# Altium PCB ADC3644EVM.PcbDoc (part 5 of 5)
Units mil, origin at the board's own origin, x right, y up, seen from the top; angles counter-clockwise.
Board outline 3900 x 2716.54 mil, 10 copper layers (Top Layer, L2 GND, L3 PWR, L4 GND, L5 SIG, L6 GND, L7 GND, L8 PWR, L9 GND, Bottom Layer), stack 61.2 mil thick; 368 components, 252 nets, 1539 pads, 1019 vias.
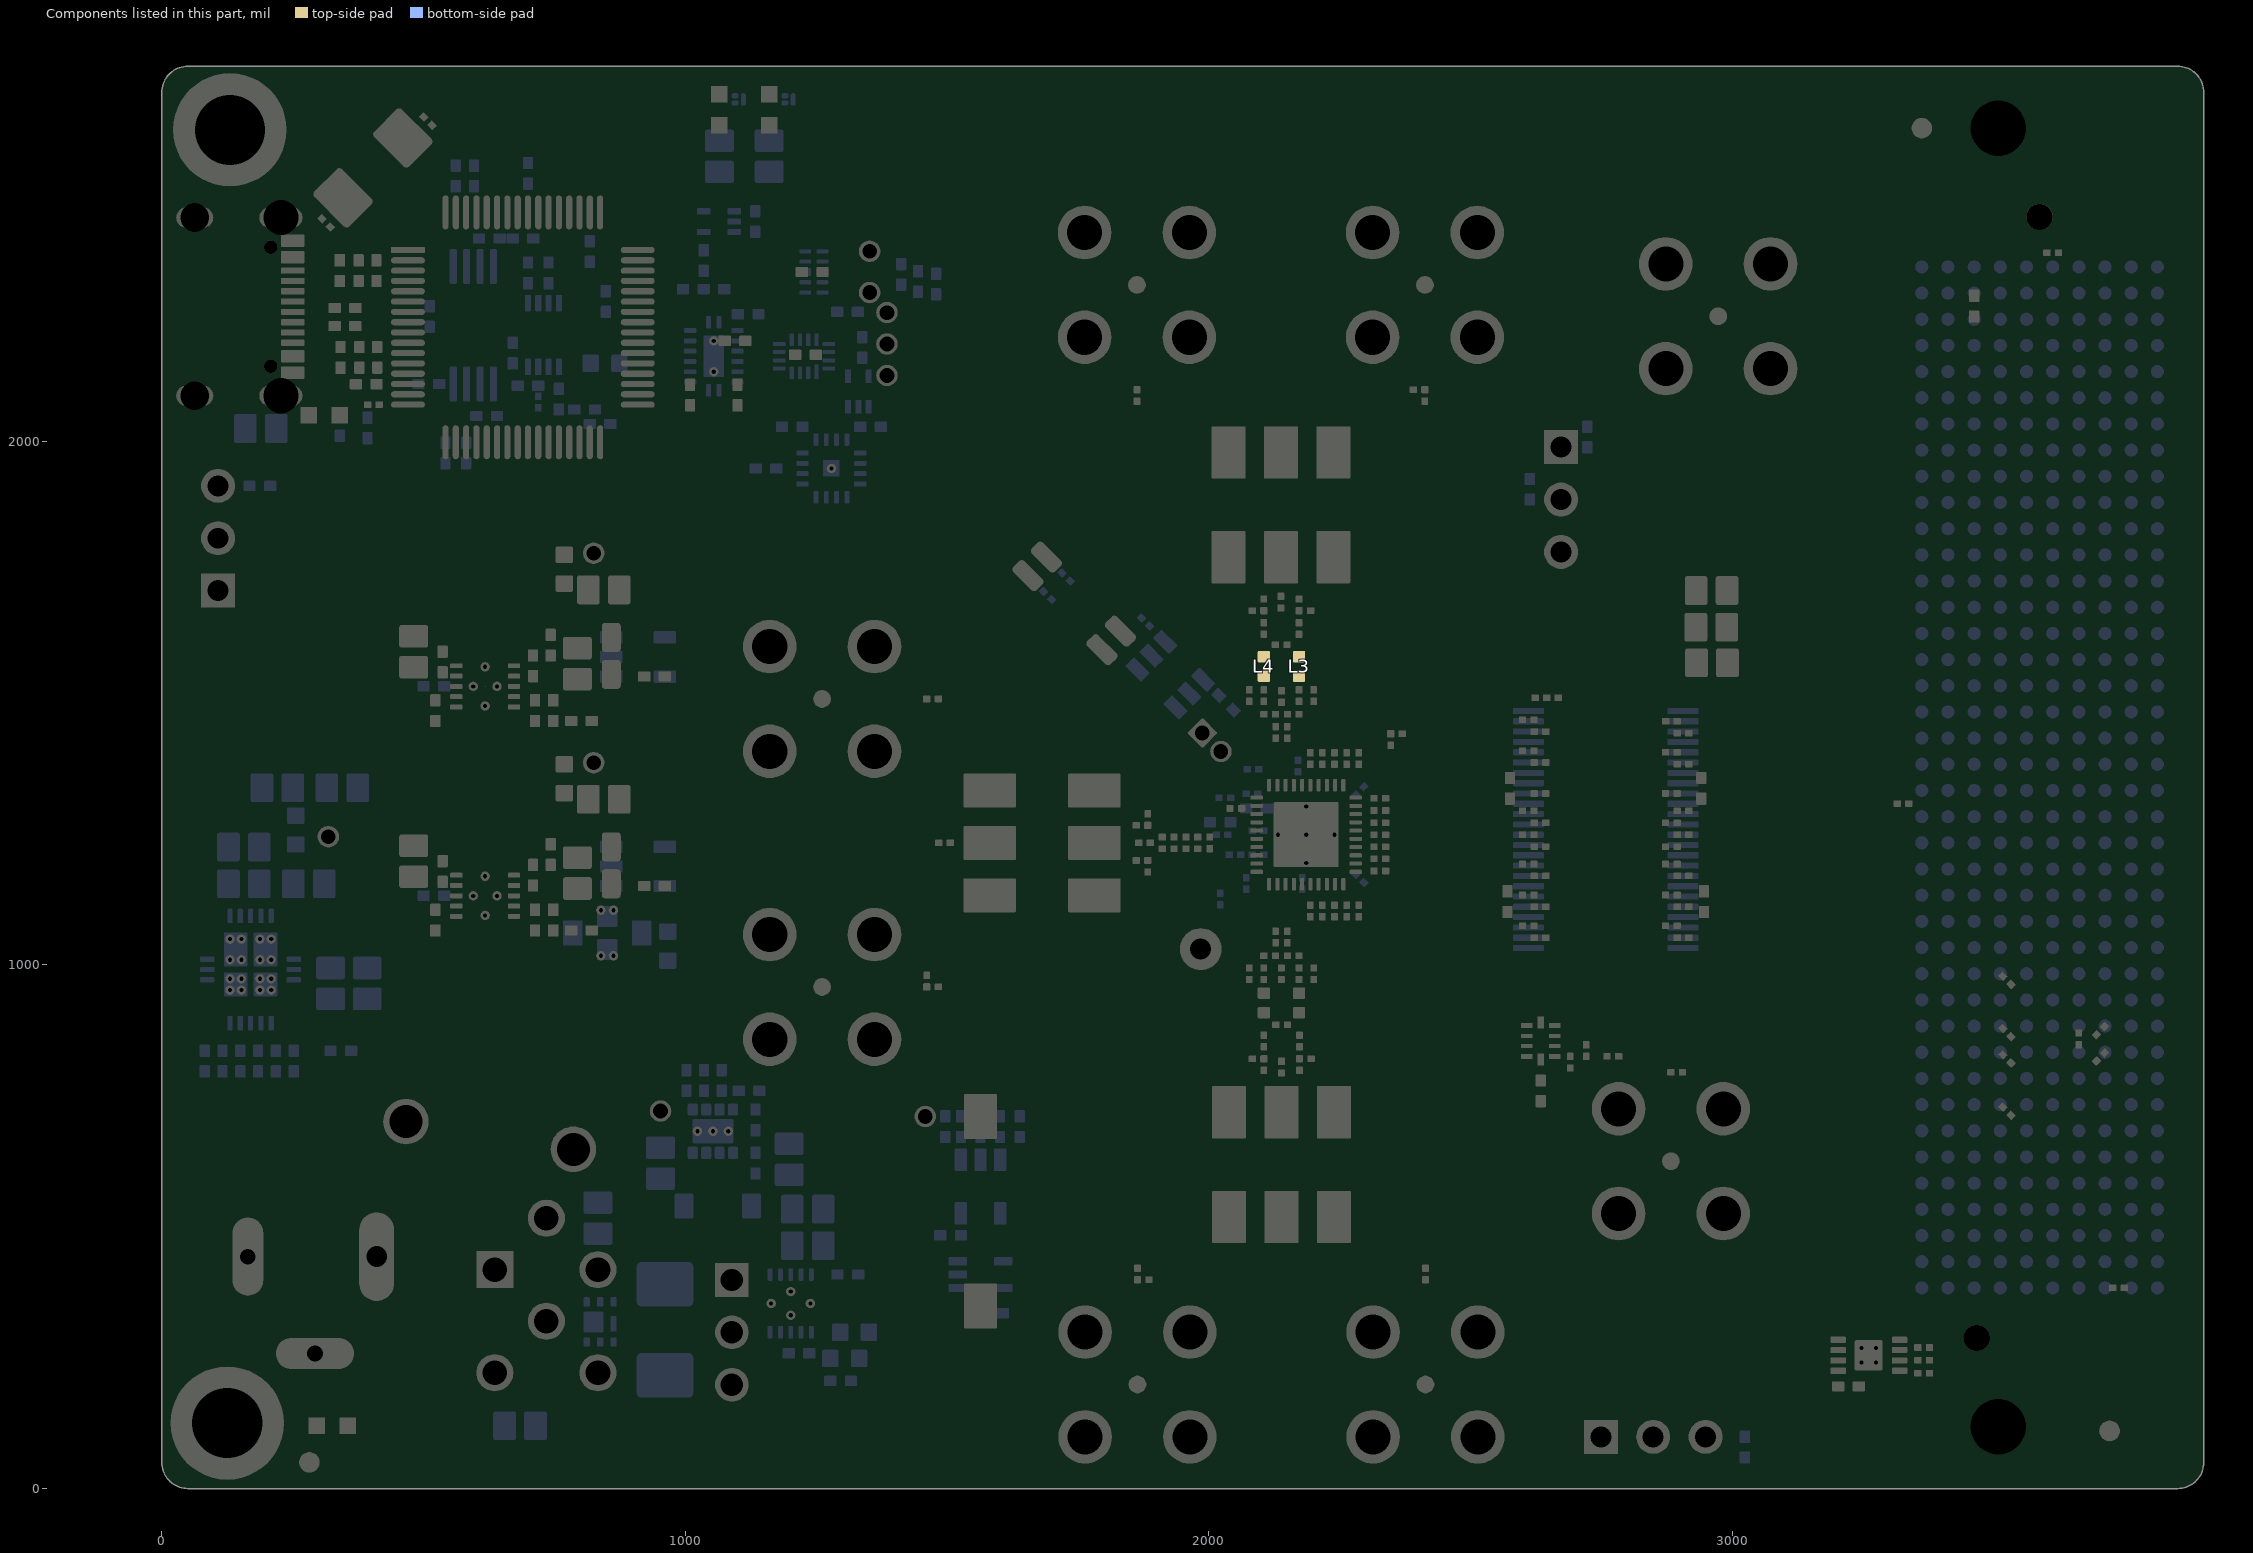
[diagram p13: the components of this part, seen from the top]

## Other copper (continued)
L3 PWR:
  pour cut-out: 2907.99,625.2 ccw(c2882.27,625.27) 2900.45,643.45 ccw(c2882.93,625.93) 2882.93,650.72 2881.55,650.72 ccw(c2881.55,625.98) 2864.06,643.47 2863.35,642.76 ccw(c2880.85,625.27) 2856.11,625.27 2856.11,624.57 ccw(c2881.56,624.57) 2863.56,606.57 2863.7,606.43 ccw(c2882.05,624.77) 2882.05,598.83 ccw(c2882.05,624.75) 2900.38,606.42 2900.75,606.79 ccw(c2883.27,624.27) 2907.99,624.27
  pour cut-out: 2998.18,2238.8 ccw(c2972.46,2238.88) 2990.65,2257.06 ccw(c2973.12,2239.54) 2973.12,2264.32 2971.75,2264.32 ccw(c2971.75,2239.59) 2954.26,2257.08 2953.55,2256.37 ccw(c2971.04,2238.88) 2946.3,2238.88 2946.3,2238.17 ccw(c2971.76,2238.17) 2953.76,2220.17 2953.9,2220.03 ccw(c2972.24,2238.38) 2972.24,2212.44 ccw(c2972.24,2238.36) 2990.58,2220.03 2990.94,2220.4 ccw(c2973.47,2237.87) 2998.18,2237.87
  pour cut-out: 2261.36,1436.62 cw(c2261.36,1447.62) 2250.36,1447.62 cw(c2261.36,1447.62) 2261.36,1458.62 cw(c2261.36,1447.62) 2272.36,1447.62 cw(c2261.36,1447.62)
  pour cut-out: 2216.16,1436.62 cw(c2216.16,1447.62) 2205.16,1447.62 cw(c2216.16,1447.62) 2216.16,1458.62 cw(c2216.16,1447.62) 2227.16,1447.62 cw(c2216.16,1447.62)
  pour cut-out: 2180.47,1425.31 cw(c2180.47,1436.31) 2169.47,1436.31 cw(c2180.47,1436.31) 2180.47,1447.31 cw(c2180.47,1436.31) 2191.47,1436.31 cw(c2180.47,1436.31)
  pour cut-out: 2198.41,1445.49 cw(c2198.41,1456.49) 2187.41,1456.49 cw(c2198.41,1456.49) 2198.41,1467.49 cw(c2198.41,1456.49) 2209.41,1456.49 cw(c2198.41,1456.49)
  pour cut-out: 2207.91,1597.91 cw(c2207.91,1608.91) 2196.91,1608.91 cw(c2207.91,1608.91) 2207.91,1619.91 cw(c2207.91,1608.91) 2218.91,1608.91 cw(c2207.91,1608.91)
  pour cut-out: 2202.84,1641 cw(c2202.84,1652) 2191.84,1652 cw(c2202.84,1652) 2202.84,1663 cw(c2202.84,1652) 2213.84,1652 cw(c2202.84,1652)
  pour cut-out: 1862.46,2330.88 cw(c1862.46,2341.88) 1851.46,2341.88 cw(c1862.46,2341.88) 1862.46,2352.88 cw(c1862.46,2341.88) 1873.46,2341.88 cw(c1862.46,2341.88)
  pour cut-out: 2412.46,2330.88 cw(c2412.46,2341.88) 2401.46,2341.88 cw(c2412.46,2341.88) 2412.46,2352.88 cw(c2412.46,2341.88) 2423.46,2341.88 cw(c2412.46,2341.88)
  pour cut-out: 2442.87,2318.28 cw(c2442.87,2329.28) 2431.87,2329.28 cw(c2442.87,2329.28) 2442.87,2340.28 cw(c2442.87,2329.28) 2453.87,2329.28 cw(c2442.87,2329.28)
  pour cut-out: 2382.06,2318.28 cw(c2382.06,2329.28) 2371.06,2329.28 cw(c2382.06,2329.28) 2382.06,2340.28 cw(c2382.06,2329.28) 2393.06,2329.28 cw(c2382.06,2329.28)
  pour cut-out: 1892.87,2318.28 cw(c1892.87,2329.28) 1881.87,2329.28 cw(c1892.87,2329.28) 1892.87,2340.28 cw(c1892.87,2329.28) 1903.87,2329.28 cw(c1892.87,2329.28)
  pour cut-out: 1832.06,2318.28 cw(c1832.06,2329.28) 1821.06,2329.28 cw(c1832.06,2329.28) 1832.06,2340.28 cw(c1832.06,2329.28) 1843.06,2329.28 cw(c1832.06,2329.28)
  pour cut-out: 921.46,1139.75 cw(c921.46,1150.75) 910.46,1150.75 cw(c921.46,1150.75) 921.46,1161.75 cw(c921.46,1150.75) 932.46,1150.75 cw(c921.46,1150.75)
  pour cut-out: 3761.42,822.27 cw(c3761.42,833.27) 3750.42,833.27 cw(c3761.42,833.27) 3761.42,844.27 cw(c3761.42,833.27) 3772.42,833.27 cw(c3761.42,833.27)
  pour cut-out: 3561.42,722.27 cw(c3561.42,733.27) 3550.42,733.27 cw(c3561.42,733.27) 3561.42,744.27 cw(c3561.42,733.27) 3572.42,733.27 cw(c3561.42,733.27)
  pour cut-out: 3560.12,570.57 cw(c3560.12,581.57) 3549.12,581.57 cw(c3560.12,581.57) 3560.12,592.57 cw(c3560.12,581.57) 3571.12,581.57 cw(c3560.12,581.57)
  pour cut-out: 3561.42,422.27 cw(c3561.42,433.27) 3550.42,433.27 cw(c3561.42,433.27) 3561.42,444.27 cw(c3561.42,433.27) 3572.42,433.27 cw(c3561.42,433.27)
  pour cut-out: 2383.73,356.91 cw(c2383.73,367.91) 2372.73,367.91 cw(c2383.73,367.91) 2383.73,378.91 cw(c2383.73,367.91) 2394.73,367.91 cw(c2383.73,367.91)
  pour cut-out: 2443.17,362.52 cw(c2443.17,373.52) 2432.17,373.52 cw(c2443.17,373.52) 2443.17,384.52 cw(c2443.17,373.52) 2454.17,373.52 cw(c2443.17,373.52)
  pour cut-out: 1978.88,358 cw(c1978.88,369) 1967.88,369 cw(c1978.88,369) 1978.88,380 cw(c1978.88,369) 1989.88,369 cw(c1978.88,369)
  pour cut-out: 1920.88,358 cw(c1920.88,369) 1909.88,369 cw(c1920.88,369) 1920.88,380 cw(c1920.88,369) 1931.88,369 cw(c1920.88,369)
  pour cut-out: 1893.17,362.52 cw(c1893.17,373.52) 1882.17,373.52 cw(c1893.17,373.52) 1893.17,384.52 cw(c1893.17,373.52) 1904.17,373.52 cw(c1893.17,373.52)
  pour cut-out: 1833.73,356.91 cw(c1833.73,367.91) 1822.73,367.91 cw(c1833.73,367.91) 1833.73,378.91 cw(c1833.73,367.91) 1844.73,367.91 cw(c1833.73,367.91)
  pour cut-out: 1824.06,1413.46 cw(c1824.06,1424.46) 1813.06,1424.46 cw(c1824.06,1424.46) 1824.06,1435.46 cw(c1824.06,1424.46) 1835.06,1424.46 cw(c1824.06,1424.46)
  pour cut-out: 2063.68,1013.29 cw(c2063.68,1024.29) 2052.68,1024.29 cw(c2063.68,1024.29) 2063.68,1035.29 cw(c2063.68,1024.29) 2074.68,1024.29 cw(c2063.68,1024.29)
  pour cut-out: 2260.18,1245.67 cw(c2260.18,1256.67) 2249.18,1256.67 cw(c2260.18,1256.67) 2260.18,1267.67 cw(c2260.18,1256.67) 2271.18,1256.67 cw(c2260.18,1256.67)
  pour cut-out: 2244.75,1214.18 cw(c2244.75,1225.18) 2233.75,1225.18 cw(c2244.75,1225.18) 2244.75,1236.18 cw(c2244.75,1225.18) 2255.75,1225.18 cw(c2244.75,1225.18)
  pour cut-out: 1980.33,1776.9 cw(c1980.33,1787.9) 1969.33,1787.9 cw(c1980.33,1787.9) 1980.33,1798.9 cw(c1980.33,1787.9) 1991.33,1787.9 cw(c1980.33,1787.9)
  pour cut-out: 1836.08,1780.35 cw(c1836.08,1791.35) 1825.08,1791.35 cw(c1836.08,1791.35) 1836.08,1802.35 cw(c1836.08,1791.35) 1847.08,1791.35 cw(c1836.08,1791.35)
  pour cut-out: 1888.18,2298.8 ccw(c1862.46,2298.88) 1880.65,2317.06 ccw(c1863.12,2299.54) 1863.12,2324.32 1861.75,2324.32 ccw(c1861.75,2299.59) 1844.26,2317.08 1843.55,2316.37 ccw(c1861.04,2298.88) 1836.3,2298.88 1836.3,2298.17 ccw(c1861.76,2298.17) 1843.76,2280.17 1843.9,2280.03 ccw(c1862.24,2298.38) 1862.24,2272.44 ccw(c1862.24,2298.36) 1880.58,2280.03 1880.94,2280.4 ccw(c1863.47,2297.87) 1888.18,2297.87
  pour cut-out: 2438.18,2298.8 ccw(c2412.46,2298.88) 2430.65,2317.06 ccw(c2413.12,2299.54) 2413.12,2324.32 2411.75,2324.32 ccw(c2411.75,2299.59) 2394.26,2317.08 2393.55,2316.37 ccw(c2411.04,2298.88) 2386.3,2298.88 2386.3,2298.17 ccw(c2411.76,2298.17) 2393.76,2280.17 2393.9,2280.03 ccw(c2412.24,2298.38) 2412.24,2272.44 ccw(c2412.24,2298.36) 2430.58,2280.03 2430.94,2280.4 ccw(c2413.47,2297.87) 2438.18,2297.87
  pour cut-out: 2387.73,198.79 ccw(c2413.44,198.72) 2395.26,180.53 ccw(c2412.79,198.06) 2412.79,173.27 2414.16,173.27 ccw(c2414.16,198) 2431.65,180.52 2432.36,181.23 ccw(c2414.86,198.72) 2439.61,198.72 2439.61,199.42 ccw(c2414.15,199.42) 2432.15,217.42 2432.01,217.56 ccw(c2413.67,199.22) 2413.67,225.16 ccw(c2413.67,199.23) 2395.33,217.57 2394.97,217.2 ccw(c2412.44,199.72) 2387.73,199.72
  pour cut-out: 1837.73,198.79 ccw(c1863.44,198.72) 1845.26,180.53 ccw(c1862.79,198.06) 1862.79,173.27 1864.16,173.27 ccw(c1864.16,198) 1881.65,180.52 1882.36,181.23 ccw(c1864.86,198.72) 1889.61,198.72 1889.61,199.42 ccw(c1864.15,199.42) 1882.15,217.42 1882.01,217.56 ccw(c1863.67,199.22) 1863.67,225.16 ccw(c1863.67,199.23) 1845.33,217.57 1844.97,217.2 ccw(c1862.44,199.72) 1837.73,199.72
  pour cut-out: 1261.18,983.77 ccw(c1261.11,958.05) 1242.92,976.24 ccw(c1260.45,958.71) 1235.66,958.71 1235.66,957.33 ccw(c1260.39,957.33) 1242.9,939.85 1243.61,939.14 ccw(c1261.11,956.63) 1261.11,931.89 1261.81,931.89 ccw(c1261.81,957.35) 1279.81,939.35 1279.95,939.49 ccw(c1261.61,957.83) 1287.55,957.83 ccw(c1261.62,957.83) 1279.95,976.16 1279.59,976.53 ccw(c1262.11,959.05) 1262.11,983.77
  pour cut-out: 1261.18,1533.77 ccw(c1261.11,1508.05) 1242.92,1526.24 ccw(c1260.45,1508.71) 1235.66,1508.71 1235.66,1507.33 ccw(c1260.39,1507.33) 1242.9,1489.85 1243.61,1489.14 ccw(c1261.11,1506.63) 1261.11,1481.89 1261.81,1481.89 ccw(c1261.81,1507.35) 1279.81,1489.35 1279.95,1489.49 ccw(c1261.61,1507.83) 1287.55,1507.83 ccw(c1261.62,1507.83) 1279.95,1526.16 1279.59,1526.53 ccw(c1262.11,1509.05) 1262.11,1533.77
  pour cut-out: 2074.96,1833.88 2074.96,1723.88 1999.96,1723.88 1999.96,1833.88
  pour cut-out: 2274.96,1833.88 2274.96,1723.88 2199.96,1723.88 2199.96,1833.88
  pour cut-out: 2274.96,2033.88 2274.96,1923.88 2199.96,1923.88 2199.96,2033.88
  pour cut-out: 2200.95,663.72 2200.95,773.72 2275.95,773.72 2275.95,663.72
  pour cut-out: 2000.95,663.72 2000.95,773.72 2075.95,773.72 2075.95,663.72
  pour cut-out: 2000.95,463.72 2000.95,573.72 2075.95,573.72 2075.95,463.72
  pour cut-out: 1726.11,1295.55 1836.11,1295.55 1836.11,1370.55 1726.11,1370.55
  pour cut-out: 1726.11,1095.55 1836.11,1095.55 1836.11,1170.55 1726.11,1170.55
  pour cut-out: 1526.11,1095.55 1636.11,1095.55 1636.11,1170.55 1526.11,1170.55
  text ".Layer_Name" at 575,-860 h60
L4 GND:
  text ".Layer_Name" at 575,-860 h60
L7 GND:
  text ".Layer_Name" at 575,-860 h60
L8 PWR:
  pour cut-out: 3220.57,234.09 cw(c3220.57,245.09) 3209.57,245.09 cw(c3220.57,245.09) 3220.57,256.09 cw(c3220.57,245.09) 3231.57,245.09 cw(c3220.57,245.09)
  pour cut-out: 3246.08,229.6 cw(c3246.08,240.6) 3235.08,240.6 cw(c3246.08,240.6) 3246.08,251.6 cw(c3246.08,240.6) 3257.08,240.6 cw(c3246.08,240.6)
  pour cut-out: 3381.1,258.36 cw(c3381.1,269.36) 3370.1,269.36 cw(c3381.1,269.36) 3381.1,280.36 cw(c3381.1,269.36) 3392.1,269.36 cw(c3381.1,269.36)
  pour cut-out: 3381.1,233.68 cw(c3381.1,244.68) 3370.1,244.68 cw(c3381.1,244.68) 3381.1,255.68 cw(c3381.1,244.68) 3392.1,244.68 cw(c3381.1,244.68)
  text ".Layer_Name" at 575,-860 h60
L9 GND:
  text ".Layer_Name" at 575,-860 h60
L5 SIG:
  pour cut-out: 2229.69,1544.16 cw(c2229.69,1555.16) 2218.69,1555.16 cw(c2229.69,1555.16) 2229.69,1566.16 cw(c2229.69,1555.16) 2240.69,1555.16 cw(c2229.69,1555.16)
  pour cut-out: 289 vertices and 0 holes, not listed, extent 1474.6,1637.11 2479.44,2122.9
  text ".Layer_Name" at 575,-860 h60
L6 GND:
  text ".Layer_Name" at 575,-860 h60
Bottom Layer:
  region net GND: 1059.37,2237.86 cw(c1060.67,2237.86) 1060.67,2239.16 1066.77,2239.16 1066.77,2239.28 1107.06,2239.28 cw(c1107.06,2235.01) 1111.34,2235.01 1111.34,2208.52 cw(c1109.9,2208.52) 1109.9,2207.08 1090.08,2207.08 1090.08,2207 1070.2,2207 cw(c1070.2,2217.83) 1059.37,2217.83
  region net 1p8V_BUFVCC: 1023.43,1037.43 ccw(c1023.43,1044.73) 1030.73,1044.73 1030.73,1079.23 ccw(c1025.3,1079.23) 1025.3,1084.67 900.29,1084.67 ccw(c900.29,1082.16) 897.78,1082.16 897.78,1039.27 ccw(c899.62,1039.27) 899.62,1037.43 929.59,1037.43 931.49,1037.43
  region net 1p8V_LVLSHIFT: 801.22,1037.43 ccw(c801.22,1039.5) 803.29,1039.5 803.29,1111.35 cw(c813.86,1111.35) 813.86,1121.91 ccw(c813.86,1129.14) 821.09,1129.14 821.09,1165.8 ccw(c817.44,1165.8) 817.44,1169.45 774.38,1169.45 ccw(c774.38,1160.96) 765.89,1160.96 765.89,1039.69 ccw(c768.16,1039.69) 768.16,1037.43
  region net NetJ3_A4,B4: 225,2165 ccw(c240,2165) 240,2150 265,2150 ccw(c265,2160) 275,2160 275,2355 ccw(c265,2355) 265,2365 240.09,2365 ccw(c240,2350) 225,2350 225,2320 cw(c205,2320) 205,2300 140,2300 ccw(c140,2280) 120,2280 120,2020 ccw(c145,2020) 145,1995 180,1995 ccw(c180,2000) 185,2000 185,2055 ccw(c180,2055) 180,2060 cw(c180,2070) 170,2070 170,2165 cw(c180,2165) 180,2175 215,2175 cw(c215,2165)
  region net GND: 1358.66,1933.73 ccw(c1358.66,1938.23) 1363.17,1938.23 1363.17,1958.63 ccw(c1358.94,1958.63) 1358.94,1962.86 1324.07,1962.86 ccw(c1324.07,1961) 1322.21,1961 1322.21,1935.65 ccw(c1324.13,1935.65) 1324.13,1933.73 1326.09,1933.73
  region net 3p3V_Utility: 1199.13,1962.86 ccw(c1199.13,1958.36) 1194.62,1958.36 1194.62,1937.96 ccw(c1198.85,1937.96) 1198.85,1933.73 1233.72,1933.73 ccw(c1233.72,1935.59) 1235.58,1935.59 1235.58,1960.93 ccw(c1233.66,1960.93) 1233.66,1962.86 1231.7,1962.86
  region net 3p3V_Utility: 1053.66,2073.3 1064.09,2073.3 ccw(c1064.09,2078.02) 1068.82,2078.02 1068.82,2104.88 1068.82,2107.09 ccw(c1066.69,2107.24) 1066.83,2109.36 1030.72,2109.36 ccw(c1030.72,2098.63) 1019.99,2098.63 1019.99,2096.93 ccw(c1028.57,2096.93) 1028.57,2088.35 cw(c1028.57,2083.37) 1033.55,2083.37 ccw(c1043.62,2083.37) 1043.62,2073.3 1044.15,2073.3 ccw(c1044.15,2097.97) 1046.76,2073.44 1046.61,2073.3
  region net DC-DC_PG: 242.05,824.31 242.05,870.61 ccw(c237.5,870.61) 237.5,875.16 231.59,875.16 cw(c231.59,877.12) 229.62,877.12 229.62,909.61 cw(c231.59,909.61) 231.59,911.57 264.07,911.57 cw(c264.07,909.8) 265.84,909.8 265.84,903.7 266.04,903.7 266.04,828.62 cw(c261.73,828.62) 261.73,824.31
  region net 2p3V: 294.81,1210.12 cw(c294.81,1214.32) 290.61,1214.32 290.61,1249.02 ccw(c270.2,1249.02) 270.2,1269.44 238.85,1269.44 cw(c238.85,1279.62) 228.67,1279.62 228.67,1420.85 cw(c235.57,1420.85) 235.57,1427.76 327.39,1427.76 cw(c327.39,1418.21) 336.94,1418.21 336.94,1281.99 ccw(c345.07,1281.99) 345.07,1273.85 cw(c345.07,1266.38) 352.54,1266.38 352.54,1217.59 cw(c345.07,1217.59) 345.07,1210.12
  region net GND: 38.05,863.68 38.05,968.87 cw(c45.17,968.87) 45.17,976 98.72,976.54 ccw(c98.72,986.95) 109.13,986.95 109.13,997.24 ccw(c99.52,996.45) 98.72,1006.06 45.17,1006.06 cw(c44.84,1012.86) 38.05,1012.53 38.26,1115.78 cw(c47.89,1115.78) 47.89,1125.41 103.58,1125.41 ccw(c103.58,1127.44) 105.61,1127.44 105.61,1182.56 148.91,1182.56 148.91,1123.39 ccw(c152.85,1123.39) 152.85,1119.46 cw(c152.85,1117.49) 154.82,1117.49 154.82,1074.55 ccw(c158.26,1074.55) 158.26,1071.11 cw(c158.26,1065.7) 163.68,1065.7 163.68,997.8 ccw(c176.56,998.24) 175.49,985.39 218.73,985.39 cw(c218.73,983.36) 220.76,983.36 220.76,884.02 cw(c211.91,884.01) 211.91,875.16 206,875.16 cw(c206,877.12) 204.03,877.13 204.03,909.64 ccw(c199.05,909.64) 199.05,914.62 114.55,914.62 ccw(c114.55,909.61) 109.54,909.61 109.54,887.21 cw(c86.02,887.2) 86.01,863.68
  region net GND: 240.5,966.69 275.71,966.69 ccw(c275.71,970.29) 279.3,970.29 cw(c281.61,970.29) 281.61,972.6 419.82,972.6 419.82,1015.85 283.36,1015.85 cw(c263.68,1015.9) 263.68,996.22 240.42,996.22 ccw(c240.42,994.29) 238.48,994.29 238.48,971.09 238.48,968.57 ccw(c240.35,968.57) 240.35,966.7
  region net 12V: 238.48,955.68 cw(c239.65,955.68) 239.65,956.85 419.82,956.85 419.82,913.54 294.7,913.54 ccw(c280.92,913.54) 280.92,927.32 240.43,927.32 cw(c240.25,929.09) 238.48,928.91
  region net NetC11_2: 164.66,1213.92 164.66,1252.86 cw(c170.05,1252.86) 170.05,1258.25 267.23,1258.25 cw(c267.23,1252.56) 272.93,1252.56 272.93,1014.92 cw(c264.07,1014.92) 264.07,1006.06 240.45,1006.06 227.58,1006.06 ccw(c227.58,999.24) 220.76,999.24 cw(c218.73,999.24) 218.73,997.2 177.53,997.2 cw(c177.53,999.24) 175.49,999.24 175.49,1070.83 ccw(c166.43,1070.83) 166.63,1079.88 cw(c166.63,1081.88) 166.55,1079.88 ccw(c166.55,1079.78) 166.53,1079.88 cw(c166.63,1081.85) 164.66,1081.85 164.66,1213.87 cw(c174.84,1213.87)
  pour cut-out: 109.54,877.13 109.54,909.61 cw(c114.55,909.61) 114.55,914.62 199.05,914.62 cw(c199.05,909.64) 204.03,909.64 204.03,877.13
  region net 12V: 1085.37,563.37 cw(c1085.37,544.99) 1103.76,544.99 1103.76,522.42 ccw(c1110.83,522.42) 1110.83,515.35 1137.61,515.35 cw(c1137.61,495.83) 1157.12,495.83 1157.12,400 ccw(c1160.29,400) 1160.29,396.83 1203.8,396.83 ccw(c1203.8,398.96) 1205.94,398.97 1205.94,426.28 cw(c1215.74,426.28) 1215.74,436.08 1225.69,436.08 1225.69,616.62 ccw(c1221.29,616.62) 1221.29,621.02 1175.14,621.02 ccw(c1175.14,607.73) 1175.08,621.02 1087.64,621.02 cw(c1087.64,633.52) 1075.13,633.52 1075.13,648.1 ccw(c1070.28,648.1) 1070.28,652.96 1060.06,652.96 ccw(c1060.06,648.35) 1055.45,648.35 1055.45,567 ccw(c1059.07,567) 1059.07,563.37
  region net NetF1_1: 679.61,584.11 680.09,584.03 825.56,584.03 ccw(c825.56,617.33) 858.86,617.33 858.86,707.08 ccw(c852.59,707.08) 852.59,713.36 577.66,713.36 ccw(c577.66,693) 557.31,693 557.31,585.32 cw(c517.94,585.32) 517.94,545.95 389.99,545.95 ccw(c389.99,516.43) 360.46,516.43 360.46,378.63 ccw(c409.67,378.63) 409.67,329.42 618.33,329.42 ccw(c618.33,382.57) 671.48,382.57 671.48,571.54 cw(c685.26,571.54)
  region net EXTGND: 101.33,287.03 ccw(c124.78,287.03) 124.78,263.57 182.11,263.57 cw(c182.11,238.64) 207.04,238.64 ccw(c229.51,238.64) 229.51,216.17 531.41,216.17 cw(c531.41,188.72) 558.86,188.72 ccw(c573.91,188.72) 573.91,173.67 669.83,173.67 ccw(c669.83,189.11) 685.26,189.11 685.26,287.03 633.15,287.03 cw(c633.15,296.61) 633.1,287.03 685.26,287.03 ccw(c659.66,284.13) 656.76,309.73 350.62,309.73 cw(c350.62,319.58) 340.77,319.58 340.77,496.72 340.87,496.74 340.87,530.41 340.87,547.77 cw(c410.43,547.78) 410.43,617.33 491.45,617.33 ccw(c491.45,662.2) 536.33,662.2 536.33,740.36 ccw(c493.33,740.36) 493.33,783.36 391.33,783.36 ccw(c391.32,678.36) 286.38,681.78 286.33,681.8 cw(c143.89,681.79) 144.13,539.36 113.59,539.36 ccw(c113.59,527.1) 101.33,527.1
  region net NetR1_2: 1208.88,248.56 1208.88,268.25 cw(c1208.88,271.24) 1205.89,271.24 1205.89,307.98 1205.94,307.98 1205.94,308.31 ccw(c1204.03,308.31) 1204.03,310.21 1159.38,310.21 1129.39,310.21 cw(c1129.39,318.62) 1120.99,318.62 ccw(c1109.11,318.62) 1109.11,330.49 1062.92,330.49 ccw(c1062.92,324.33) 1056.76,324.33 1056.76,256.47 ccw(c1064.67,256.47) 1064.67,248.56 1185.4,248.56
  region net GND: 858.86,270.91 878.85,270.91 ccw(c878.85,278.48) 886.42,278.48 886.42,315.7 ccw(c872.93,315.7) 872.93,329.18 857.49,329.18 857.49,328.61 856.92,328.61 856.92,272.86 ccw(c858.86,272.86)
  region net NetC1_2: 695.1,299.89 ccw(c724.63,299.89) 724.63,270.36 cw(c724.63,231) 764,230.99 764,211.31 ccw(c793.5,211.31) 764.08,209.13 ccw(c767.36,208.4) 764,208.4 ccw(c798.74,208.4) 798.74,173.67 1005.49,173.67 996.33,188.72 996.32,255.77 850.23,255.77 cw(c850.93,263.53) 843.14,263.53 843.14,362.9 ccw(c840.64,362.91) 840.64,365.4 787.07,365.4 cw(c787.07,378.63) 773.85,378.63 773.85,506.59 cw(c793.53,506.59) 774.03,509.31 774.03,508.51 cw(c789.84,508.51) 774.07,509.54 cw(c793.53,506.59) 779.95,520.84 cw(c789.84,508.51) 789.84,524.31 805.34,524.31 805.34,524.3 860.46,524.3 ccw(c860.46,526.27) 862.43,526.27 862.43,536.11 862.43,561.2 862.43,564.87 ccw(c859.69,564.87) 859.69,567.61 701.51,567.61 ccw(c701.51,561.2) 695.1,561.2
  region net NetC5_2: 1311.06,281.67 1311.06,315.14 1268.26,315.14 ccw(c1268.26,313.4) 1266.53,313.4 cw(c1263.34,313.4) 1263.34,310.21 1237.85,310.21 ccw(c1237.85,308.23) 1235.86,308.23 1235.86,288.58 ccw(c1237.85,288.58) 1237.85,286.59 1264.6,286.59 cw(c1264.6,284.62) 1266.57,284.62 ccw(c1269.52,284.62) 1269.52,281.67 1279.56,281.67
  region net NetC4_2: 1216.2,281.52 ccw(c1217.68,281.52) 1217.68,280.04 cw(c1217.68,278.79) 1218.93,278.79 1218.93,251.79 ccw(c1222.16,251.79) 1221.52,248.62 1221.52,248.56 1235.02,248.56 cw(c1235.02,232.36) 1251.22,232.36 1251.22,210.14 ccw(c1265.58,210.14) 1265.58,195.78 1288.75,195.78 1288.75,228.14 cw(c1292.28,228.14) 1292.28,231.67 1292.28,265.14 1251.3,265.14 cw(c1251.3,268.18) 1248.25,268.18 1245.58,268.18 cw(c1245.58,288.17) 1225.58,288.17 1225.58,308.49 ccw(c1223.88,308.49) 1223.88,310.21 1217.89,310.21 ccw(c1217.89,308.52) 1216.2,308.52 1216.2,289.12 1216.18,289.12 1216.18,288.01 ccw(c1217.47,288.01) 1216.2,287.78
  region net 3p3V_Utility: 1009.61,629.34 1020.57,629.34 ccw(c1020.57,632.67) 1023.91,632.67 1023.91,650.05 ccw(c1020.91,650.05) 1020.91,652.96 1008.74,652.96 cw(c1008.74,660.8) 1000.91,660.8 1000.91,705.19 cw(c1007.76,705.19) 1007.76,712.04 1020.08,712.04 ccw(c1020.08,715.91) 1023.95,715.91 1023.95,731.69 ccw(c1020,731.69) 1020,735.64 1007.66,735.64 1007.66,735.6 981.49,735.6 cw(c981.49,744.6) 972.5,744.6 ccw(c968.34,744.6) 968.34,748.75 932.5,748.75 ccw(c932.5,741.19) 924.94,741.19 924.94,632.96 ccw(c928.49,632.96) 928.49,629.41 1017.11,629.41
  region net NetC1_1: 793.53,382.57 ccw(c797.47,382.57) 797.47,378.63 847.74,378.63 cw(c847.74,369.45) 856.92,369.45 856.92,351.27 ccw(c860.5,351.27) 860.5,347.69 1015.01,347.69 1030.73,347.69 ccw(c1030.73,356.54) 1039.59,356.54 cw(c1049.53,356.54) 1049.53,366.48 1120.99,366.48 1120.99,466.92 ccw(c1101.01,466.92) 1101.01,486.9 921.48,486.9 cw(c921.48,496.74) 911.64,496.74 ccw(c899.83,496.74) 899.83,508.55 805.34,508.55 ccw(c805.34,496.74) 793.53,496.74
  region net 3p3V_Utility: 532.01,1988.54 ccw(c534.67,1988.54) 534.67,1985.88 603.73,1985.88 ccw(c603.73,1994.84) 612.68,1994.84 612.68,2056.34 ccw(c610.86,2056.34) 610.86,2058.16 540.49,2058.16 ccw(c540.55,2049.62) 532.01,2049.77 532.01,1999.41
  region net 3p3V_Utility: 519.77,2097.73 531.52,2097.73 cw(c531.52,2079.52) 549.72,2079.52 ccw(c553.17,2079.52) 553.17,2076.08 560.06,2076.08 ccw(c560.06,2079.52) 563.5,2079.52 563.5,2139.56 ccw(c560.06,2139.56) 560.06,2143.01 553.17,2143.01 ccw(c553.17,2139.56) 549.72,2139.56 cw(c531.52,2139.56) 531.52,2121.35 519.77,2121.35
  region net GND: 638.66,2076.08 ccw(c638.66,2089.5) 652.09,2089.5 652.09,2129.23 ccw(c638.31,2129.23) 638.31,2143.01 629.94,2143.01 ccw(c629.94,2139.56) 626.5,2139.56 626.5,2079.52 ccw(c629.94,2079.52) 629.94,2076.08
  pour cut-out: 264 vertices and 0 holes, not listed, extent 2633.31,840.66 3489.35,2225.71
  pour cut-out: 494 vertices and 0 holes, not listed, extent 2648.54,805.06 3554.21,1460.91
  pour cut-out: 278 vertices and 0 holes, not listed, extent 2772.2,1087.03 3689.35,2126.06
  pour cut-out: 2582.24,1434.61 2576.45,1428.81 2576.45,1413.92 2568.49,1413.92 2559.43,1422.98 2559.43,1445.65
  pour cut-out: 2555,1330 2555,1291.25 2557.83,1288.42 2575.08,1288.42 2575.08,1322.02 2580.6,1327.54
  pour cut-out: 2560,1110 2556.51,1106.51 2556.51,1071.63 2584.91,1071.63 2586.77,1073.49 2586.77,1111
  pour cut-out: 2341.76,1166.31 2341.76,1135.32 2337.13,1130.69 2368.96,1130.69 2368.96,1168.77 2370.24,1170.06
  pour cut-out: 2565,1230 2565.89,1229.11 2580.6,1229.11 2580.6,1190.74 2579.6,1189.74 2563.29,1189.74
  pour cut-out: 2871.14,1222.34 2871.14,1194.4 2877.52,1200.78 2885.31,1200.78 2885.31,1218.07
  pour cut-out: 2860,1445 2860,1302.92 2870.62,1292.3 2883.58,1305.27 2883.58,1451.55
  pour cut-out: 3340,2040 3348.51,2048.51 3348.51,2120.92 3323.74,2120.92 3311.09,2108.27 3333.44,2085.91 3333.44,2040.13
  pour cut-out: 3186.24,830.5 3186.24,824.45 3223.95,786.75 3209.85,772.65 3186.24,772.65 3186.24,802.16 3165.55,822.85
  pour cut-out: 3350,1110 3350,1065.21 3337.37,1077.84 3337.37,1108.27
  pour cut-out: 3344.84,1226.4 3339.78,1221.34 3339.78,1158.27 3323.27,1158.27 3325.45,1160.45 3325.45,1219.45
  pour cut-out: 3350,1660 3346.86,1656.87 3346.86,1608.27 3335.97,1608.27
  pour cut-out: 2955,1230 2955,1191 2956.26,1189.74 2975.15,1189.74 2975.15,1226.13 2972.17,1229.11
  pour cut-out: 2950,1290 2950,1323.95 2953.58,1327.54 2962.52,1318.6 2962.52,1288.17
  pour cut-out: 2950,1405 2950.77,1405.77 2950.77,1470.35 2957.73,1470.35 2966.06,1462.02 2966.06,1406.28
  pour cut-out: 3348.93,1881.6 3348.93,1945.66 3336.33,1958.27 3330.56,1952.49 3330.56,1898.92 3349.17,1880.31
  pour cut-out: 3345,1745 3348.73,1748.73 3348.73,1808.27 3340.02,1808.27 3334.72,1802.97 3334.72,1749.03
  pour cut-out: 190 vertices and 0 holes, not listed, extent 2134.5,1391.36 2479.44,1685.35
  region net GND: 2086.16,1331.53 2086.16,1320.62 2098.76,1320.62 2098.76,1278.94 2122.38,1278.94 2122.38,1333.22 2086.3,1333.22 2086.3,1332.54
  pour cut-out: 81.91,1006.06 81.91,1006.07 86.89,1006.06 86.9,1006.06 100.61,1006.03 104.19,1004.88 107.07,1002.45 108.79,999.1 109.13,997.24 109.13,986.95 108.93,984.92 107.38,981.17 104.5,978.29 100.75,976.74 98.72,976.54 81.91,976.53 81.91,976.55 73.2,976.57 69.62,977.71 66.74,980.15 65.02,983.5 64.68,985.36 64.68,995.64 64.88,997.68 66.43,1001.43 69.31,1004.3 73.06,1005.86 75.09,1006.06
  text ".Layer_Name" at 577,-858.49 h60
Multi-Layer:
  pour cut-out: 1334.01,1842.77 cw(c1334.01,1853.77) 1323.01,1853.77 cw(c1334.01,1853.77) 1334.01,1864.77 cw(c1334.01,1853.77) 1345.01,1853.77 cw(c1334.01,1853.77)
  pour cut-out: 1244.37,1882.18 cw(c1244.37,1893.18) 1233.37,1893.18 cw(c1244.37,1893.18) 1244.37,1904.18 cw(c1244.37,1893.18) 1255.37,1893.18 cw(c1244.37,1893.18)

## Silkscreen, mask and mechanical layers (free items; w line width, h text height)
Top Overlay:
  drawing of 231 lines, arcs and shapes, not listed
  text "POWER / GOOD" at 1239.25,2560 h90
  text "ADC3660/4xEVM / RevG" at 2530,2485.61 h60
  text "DUT / SPI" at 1641.44,2105 h70 r90
  text "CTRL" at 997.24,1992.43 h60
  text "HIGH" at 997.23,1950.17 h60
  text "LOW" at 1129.73,1950.17 h60
  text "REF" at 1258.89,1950.47 h60
  text "CLK" at 1378.89,1950.47 h60
  text "ON" at 1032.39,1911.47 h30
  text "OFF" at 1157.39,1911.47 h30
  text "EXT" at 1287.39,1911.47 h30
  text "DIFF" at 1397.39,1911.47 h30
  text "ON" at 1032.39,1851.47 h30
  text "ON" at 1157.39,1851.47 h30
  text "INT" at 1287.39,1851.47 h30
  text "DIFF" at 1397.39,1851.47 h30
  text "OFF" at 1032.39,1795.67 h30
  text "ON" at 1157.39,1795.67 h30
  text "INT" at 1287.39,1795.67 h30
  text "SE" at 1397.39,1795.67 h30
  text "DUT OPTION" at 2900,1750 h100
  text "ADC3660" at 3035,1690 h50
  text "ADC3644" at 3035,1620 h50
  text "ADC3643" at 3035,1550 h50
  text ".Layer_Name" at 577,-858.49 h60
Bottom Overlay:
  lines w7: 1290,2305 1305,2290 ; 1290,2380 1290,2370 1305,2355 1305,2290 ; 1320,2305 1305,2290 ; 1419,2259.6 1464,2259.6
  text ".Layer_Name" at 577,-858.49 h60
Top Paste:
  text ".Layer_Name" at 577,-858.49 h60
Bottom Paste:
  text ".Layer_Name" at 577,-858.49 h60
Top Solder:
  text ".Layer_Name" at 577,-858.49 h60
  text ".Layer_Name" at 577,-858.49 h60
Bottom Solder:
  text ".Layer_Name" at 577,-858.49 h60
Drill Guide:
  text ".Layer_Name" at 577,-858.49 h60
M1 Board Outline:
  lines w5: 0,50 ccw(c50,50) 50,0 100,0 3850,0 ccw(c3850,50) 3900,50 3900,100 3900,2616.53 3900,2666.54 ccw(c3850,2666.54) 3850,2716.54 100,2716.54 50,2716.54 ccw(c50,2666.54) 0,2666.54 0,2616.53 0,100 0,50
  text ".Layer_Name" at 577,-858.49 h60
M2 Board Dimensions:
  rectangle: 125,-400 500,-275
  rectangle: 0,-275 125,-150
  lines w7: 0,-275 1000,-275 ; 125,-400 125,-150 ; 250,-400 250,-150 ; 500,-400 500,-150 ; 750,-400 750,-150 ; 0,-400 0,-150 1000,-150 1000,-400 0,-400
  text ".Layer_Name" at 577,-858.49 h60
M3 3D STEP Top:
  text ".Layer_Name" at 577,-858.49 h60
M4 3D STEP Bottom:
  text ".Layer_Name" at 577,-858.49 h60
M5 Assembly Top:
  lines w10: -292,-930.17 6308,-930.17 ; -292,-726.83 6310,-726.83 ; -292,-523.5 -292,-1133.5 3713,-1133.5 6310,-1133.5 6310,-523.5 -291.5,-523.5 -291.5,-1133.5 1284,-1133.5 ; 2173,-1133.5 2173,-523.5 ; 3440,-726.83 3440,-523.5 ; 4280,-726.83 4280,-523.5 ; 4902,-1140 4902,-937.17
  text "COMPONENTS MARKED 'DNP' SHOULD NOT BE POPULATED." at 1153.5,-318.5 h60
  text "ASSEMBLY VARIANT:" at 1153,-434 h60
  text ".VariantName" at 2189,-434 h60
  text "PCB VIEWED FROM TOP SIDE" at -228.5,-655.67 h60
  text "BOARD #:" at 2248,-655.67 h60
  text ".PRJ_Number" at 2793.5,-655.67 h60
  text "REV:" at 3638,-655.67 h60
  text ".PCB_Rev" at 3929.5,-655.67 h60
  text "SVN REV:" at 4476,-655.67 h60
  text ".VersionControl_RevNumber" at 4982,-655.67 h60
  text "PLOT NAME =" at -228.5,-1064.34 h60
  text ".plot_File_Name" at 577,-1064.34 h60
  text "GENERATED    :" at 2250,-1064.34 h60
  text ".Print_Date" at 3119.5,-1064.34 h60
  text ".Print_Time" at 3848.5,-1064.34 h60
  text "TEXAS INSTRUMENTS" at 5113,-1064.34 h60
M6 Assembly Bottom:
  lines w10: -292.5,-727.33 6309.5,-727.33 ; -290.5,-930.67 6309.5,-930.67 ; 1115.5,-1140.5 1115.5,-937.67 ; 1737.5,-727.33 1737.5,-524 ; 2577.5,-727.33 2577.5,-524 ; 3844.5,-1134 3844.5,-524 ; 4733.5,-1134 6309,-1134 6309,-524 -292.5,-524 -292.5,-1134 2304.5,-1134 6309.5,-1134 6309.5,-524
  text "COMPONENTS MARKED 'DNP' SHOULD NOT BE POPULATED." at 6102,-318 h60
  text ".VariantName" at 5058,-434 h60
  text "ASSEMBLY VARIANT:" at 6097,-434 h60
  text ".VersionControl_RevNumber" at 1035.5,-656.17 h60
  text "SVN REV:" at 1541.5,-656.17 h60
  text ".PCB_Rev" at 2088,-656.17 h60
  text "REV:" at 2379.5,-656.17 h60
  text ".PRJ_Number" at 3224,-656.17 h60
  text "BOARD #:" at 3769.5,-656.17 h60
  text "PCB VIEWED FROM BOTTOM SIDE" at 6246,-656.17 h60
  text "TEXAS INSTRUMENTS" at 904.5,-1064.84 h60
  text ".Print_Time" at 2169,-1064.84 h60
  text ".Print_Date" at 2898,-1064.84 h60
  text "GENERATED    :" at 3767.5,-1064.84 h60
  text ".plot_File_Name" at 5440.5,-1064.84 h60
  text "PLOT NAME =" at 6246,-1064.84 h60
M9 Title Sheet:
  drawing of 56 lines, arcs and shapes, not listed
  text "1" at 1058.34,13381.39 h70
  text "2" at 4384,13381.39 h70
  text "3" at 7714,13381.39 h70
  text "4" at 11049,13381.39 h70
  text "5" at 14374,13381.39 h70
  text "6" at 17709,13381.39 h70
  text "A" at -463,11603.39 h70
  text "A" at 19237,11603.39 h70
  text "B" at -463,7853.39 h70
  text "B" at 19237,7853.39 h70
  text "C" at -463,4103.39 h70
  text "C" at 19237,4103.39 h70
  text "D" at -463,353.39 h70
  text "D" at 19237,353.39 h70
  text "PROJECT TITLE:" at 16143,268.39 h45
  text ".PRJ_Title" at 16193,135.06 h70
  text "DESIGNED FOR:" at 16143,-32.61 h45
  text ".PRJ_Customer" at 16193,-172.61 h70
  text "FILE NAME:" at 16143,-332.61 h45
  text ".PCB_File_Name_No_Path" at 16193,-452.61 h70
  text "Texas Instruments (TI) and/or its licensors do not warrant the accuracy or completeness of this specification" at 11173.5,-614.45 h45
  text "ENGINEER:" at 16143,-622.61 h45
  text "LAYOUT BY:" at 17648,-622.61 h45
  text "or any information contained therein. TI and/or its licensors do not warrant that this design will meet" at 11128.51,-727.11 h45
  text ".PRJ_Engineer" at 16193,-777.6 h70
  text ".PCB_Layout" at 17698.5,-777.6 h70
  text "the specifications, will be suitable for your application or fit for any particular purpose, or will operate in" at 11128.51,-839.78 h45
  text ".Layer_Name" at 577,-858.49 h60
  text "ALTIUM DESIGNER VERSION:" at 17648,-932.61 h45
  text "an implementation. TI and/or its licensors do not warrant that the design is production worthy. You should" at 11128.51,-952.44 h45
  text "completely validate and test your design implementation to confirm the system functionality for your application." at 11173.5,-1065.11 h45
  text ".print_Scale" at 16193,-1065.94 h70
  text ".Application_BuildNumber" at 17698.5,-1065.94 h70
  text "1" at 1058.34,-1318.61 h70
  text "2" at 4384,-1318.61 h70
  text "3" at 7714,-1318.61 h70
  text "4" at 11049,-1318.61 h70
  text "5" at 14374,-1318.61 h70
  text "6" at 17709,-1318.61 h70
M10 Fab Notes:
  drawing of 213 lines, arcs and shapes, not listed
  text "M10 Fab Notes" at 16103.19,9538.99 h60
  text "DESIGN INFORMATION" at 17181.52,9421.87 h60
  text "MIN. TRACK WIDTH:" at 16536.96,9289.74 h60
  text "4" at 17633.2,9289.74 h60
  text "MIL" at 17787.96,9289.74 h60
  text "MIN. CLEARANCE:" at 16536.96,9165.62 h60
  text "MIL" at 17787.96,9165.62 h60
  text "5" at 17633.42,9163.98 h60
  text "MIN. VIA PAD SIZE:" at 16536.96,9041.49 h60
  text "18" at 17603.21,9041.49 h60
  text "MIL" at 17787.96,9041.49 h60
  text "0.05mm (2MIL)" at 17231.96,8911.59 h60
  text "MINIMUM ANNULAR RING" at 16207.73,8903.37 h60
  text "EXTERNAL" at 17939.96,8903.37 h60
  text "PER" at 16407.73,8793.24 h60
  text "IPC-D-275 CLASS 2 LEVEL C" at 16627.73,8793.24 h60
  text "MIL, HOLES" at 18115.96,8692.76 h60
  text "+/-" at 17723.5,8684.18 h60
  text "+/-" at 18577.5,8684.18 h60
  text "REGISTRATION TOLERANCES:" at 16207.73,8683.11 h60
  text "METAL" at 17407.5,8683.11 h60
  text "5" at 17983.7,8683.12 h60
  text "3" at 18816.7,8683.12 h60
  text "MIL" at 18932.96,8683.11 h60
  text "HOLE SIZE TOLERANCE (UNLESS OTHERWISE SPECIFIED):" at 16207.73,8584.8 h60
  text "+/-" at 18577.5,8581.92 h60
  text "3" at 18816.7,8580.86 h60
  text "MIL" at 18932.96,8580.86 h60
  text "MATERIAL:" at 16132.96,8443.21 h60
  text "UNIFORM STACKUP" at 17867.01,8348.29 h60
  text "X" at 17725,8345 h60
  text "HYBRID STACKUP" at 16841.48,8341.02 h60
  text "ISOLA FR408HR" at 16547.68,8177.37 h60
  text "X" at 16403.5,8170.36 h60
  text "Megtron 4    Isola I-Speed" at 16538.93,7976.12 h60
  text "OR" at 16988.92,7976.12 h60
  text "Megtron6    Isola MT-40    Nelco MW-1000" at 16538.93,7779.27 h60
  text "OR" at 16940.28,7779.27 h60
  text "OR" at 17639.01,7779.27 h60
  text "OTHER" at 16578.93,7582.42 h60
  text "X" at 16756.39,7385.94 h60
  text "62 MIL (1.6mm) +/-10%" at 16877.21,7384.84 h60
  text "92 MIL  +/-10%" at 18453.18,7384.84 h60
  text "THICKNESS:" at 16210.88,7376.62 h60
  text "OTHER" at 18162.11,7376.62 h60
  text "TOLERANCE:" at 16210.88,7238.3 h60
  text "X" at 17059.11,7238.3 h60
  text "ANSI IPC-6012 TYPE 3 CLASS 2" at 17237.12,7238.3 h60
  text "OTHER +/-" at 17237.11,7094.11 h60
  text "BOW & TWIST:" at 16210.88,6948.92 h60
  text "X" at 17059.11,6948.92 h60
  text "ANSI IPC-6012 TYPE 3 CLASS 2" at 17237.12,6948.92 h60
  text "OTHER +/-" at 17237.11,6802.23 h60
  text "DRILLING:" at 16136.11,6671.61 h60
  text "NC_DRILL FILES" at 17897.11,6566.42 h60
  text "REFERENCE:" at 16210.88,6562.48 h60
  text "X" at 16868.11,6562.39 h60
  text "AS SHOWN" at 17046.11,6562.48 h60
  text "X" at 17769.11,6562.48 h60
  text "OTHER" at 18195.11,6420.23 h60
  text "PTH COPPER THICKNESS:" at 16210.55,6416.7 h60
  text "X" at 17349.79,6416.7 h60
  text "20-30 um" at 17477.79,6416.7 h60
  text "BOARD FINISH:" at 16136.11,6269.1 h60
  text "SILKSCREEN:" at 16291.33,6158.98 h60
  text "X" at 17249.11,6158.98 h60
  text "TOP" at 17366.11,6158.98 h60
  text "X" at 17759.11,6158.98 h60
  text "BOTTOM" at 17877.11,6158.98 h60
  text "SILKSCREEN COLOR:" at 16291.33,6003.79 h60
  text "X" at 17249.11,6003.79 h60
  text "WHITE" at 17366.11,6003.79 h60
  text "OTHER" at 17877.11,6003.79 h60
  text "RED" at 18482.9,5866.47 h60
  text "X" at 17971.79,5863.76 h60
  text "GREEN" at 17497.11,5860.34 h60
  text "OTHER" at 18115.11,5860.34 h60
  text "SOLDER RESIST COLOR:" at 16291.33,5853.47 h60
  text "X" at 17379.11,5706.09 h60
  text "MATTE" at 17497.11,5706.09 h60
  text "SEMI-GLOSS" at 18114.65,5705.45 h60
  text "X" at 17009.34,5533.32 h60
  text "IMMERSION GOLD (ENIG)" at 17197.11,5533.32 h60
  text "ENEPIG" at 18534.65,5526.1 h60
  text "SURFACE FINISH:" at 16136.11,5525.1 h60
  text "IMM. TIN/SILVER OR EQUIV" at 16465.65,5387.78 h60
  text "HARD GOLD (30u)" at 17897.11,5383.84 h60
  text "OTHER" at 16490.65,5186.99 h60
  text "ARRAY/PANEL:" at 16136.11,5031.62 h60
  text "X" at 17030,5025 h60
  text "CUT AND TRIM PER M1 BOARD OUTLINE" at 17197.11,5023.39 h60
  text "N.C. ROUTE" at 17197.11,4887.43 h60
  text "V. SCORE" at 18063.11,4887.43 h60
  text "CERTIFICATION:" at 16136.11,4758.3 h60
  text "MATERIALS AND WORKMANSHIP FOR ALL PCBS" at 16861.11,4758.3 h60
  text "TO MEET OR EXCEED THE REQUIREMENTS OF:" at 16861.11,4664.24 h60
  text "X" at 16498.62,4535.61 h60
  text "ANSI IPC-A-600F CLASS ->" at 16626.61,4535.61 h60
  text "X" at 18274.62,4535.61 h60
  text "2" at 18384.61,4535.61 h60
  text "1" at 18069.61,4534.11 h60
  text "3" at 18738.61,4534.11 h60
  text "X" at 17310.62,4387.92 h60
  text "RoHS" at 17438.61,4387.92 h60
  text "OTHER" at 18083.01,4387.92 h60
  text "PER ORDER" at 18480.07,4387.92 h60
  text "ALL BOARDS MUST MEET OR EXCEED UL94-V0 REQUIREMENTS." at 16163.65,4234.1 h60
  text "PCB MUST BEAR THE UL94V-0 UL REGISTERED MATERIAL ID NUMBER" at 16163.65,4118.03 h60
  text "ADDITIONAL REQUIREMENTS:" at 16136.11,3948.61 h60
  text "MICROSECTION:" at 16210.88,3841.48 h60
  text "YES" at 17116.61,3841.48 h60
  text "REQUIRED" at 17978.11,3697.15 h60
  text "BARE BOARD ELEC. TEST:" at 16210.88,3694.29 h60
  text "NONE" at 17516.61,3694.29 h60
  text "X" at 17860.11,3694.29 h60
  text "PER ORDER" at 18570.11,3694.29 h60
  text "FAB INSTRUCTIONS" at 16207.95,3403.28 h100
  text "X" at 16255.41,3252.08 h60
  text "16 MIL & SMALLER VIAS REQUIRE NON-CONDUCTIVE FILL AND PLANARIZE" at 16362.95,3163.28 h59
  text "X" at 16254.54,3056.1 h60
  text "TOP LAYER TRACKS 9.7 MIL WIDE REQUIRE 50 OHM SINGLE-ENDED IMPEDANCE" at 16365.9,2952.65 h60
  text "OUTER LAYER TRACKS XX MIL WIDE WITH XX MIL SPACE REQUIRE 100 OHM DIFFERENTIAL IMPEDANCE" at 16365.9,2747.93 h60
  text "INNER LAYER XX & XX TRACKS XX MIL WIDE REQUIRE 50 OHM SINGLE-ENDED IMPEDANCE" at 16365.9,2543.21 h60
  text "INNER LAYER TRACKS XX MIL WIDE WITH   / XX MIL SPACE REQUIRE 100 OHM DIFFERENTIAL IMPEDANCE" at 16360,2349.31 h60
  text "NO PULL-BACK ON COPPER FEATURES TO EDGE OF THE BOARD" at 16357.04,2144.58 h60
  text ".Layer_Name" at 577,-858.49 h60
M11 Gerber Information:
  lines w10: -292,-930.17 6308,-930.17 ; -292,-726.83 6310,-726.83 ; -292,-523.5 -292,-1133.5 3713,-1133.5 6310,-1133.5 6310,-523.5 -291.5,-523.5 -291.5,-1133.5 1284,-1133.5 ; 2173,-1133.5 2173,-523.5 ; 3440,-726.83 3440,-523.5 ; 4280,-726.83 4280,-523.5 ; 4902,-1140 4902,-937.17
  text "ALL ARTWORK VIEWED FROM TOP SIDE" at -228.5,-655.67 h60
  text "BOARD #:" at 2248,-655.67 h60
  text ".PRJ_Number" at 2793.5,-655.67 h60
  text "REV:" at 3638,-655.67 h60
  text ".PCB_Rev" at 3929.5,-655.67 h60
  text "SVN REV:" at 4476,-655.67 h60
  text ".VersionControl_RevNumber" at 4982,-655.67 h60
  text "LAYER NAME =" at -228.5,-858.49 h60
  text "PLOT NAME =" at -228.5,-1064.34 h60
  text ".plot_File_Name" at 577,-1064.34 h60
  text "GENERATED    :" at 2250,-1064.34 h60
  text ".Print_Date" at 3119.5,-1064.34 h60
  text ".Print_Time" at 3848.5,-1064.34 h60
  text "TEXAS INSTRUMENTS" at 5113,-1064.34 h60
M12 Stackup:
  drawing of 607 lines, arcs and shapes, not listed
  text "Layer" at 9956.79,4031.7 h60
  text "Name" at 10366.7,4031.7 h60
  text "Material" at 11296.44,4031.7 h60
  text "Thickness" at 12156.21,4031.7 h60
  text "Constant" at 12806.04,4031.7 h60
  text "Board Layer Stack" at 13375.91,4031.7 h60
  text "Top Overlay" at 10366.7,3911.7 h60
  text "Top Solder" at 10366.7,3791.7 h60
  text "Solder Resist" at 11296.44,3791.7 h60
  text "0.40mil" at 12156.21,3791.7 h60
  text "3.5" at 12806.04,3791.7 h60
  text "1" at 9956.79,3671.7 h60
  text "Top Layer" at 10366.7,3671.7 h60
  text "1.40mil" at 12156.21,3671.7 h60
  text "Dielectric 1" at 10366.7,3551.7 h60
  text "FR408HR" at 11296.44,3551.7 h60
  text "5.00mil" at 12156.21,3551.7 h60
  text "3.62" at 12806.04,3551.7 h60
  text "2" at 9956.79,3431.7 h60
  text "L2 GND" at 10366.7,3431.7 h60
  text "CF-004" at 11296.44,3431.7 h60
  text "1.40mil" at 12156.21,3431.7 h60
  text "Dielectric 3" at 10366.7,3311.7 h60
  text "FR408HR" at 11296.44,3311.7 h60
  text "3.20mil" at 12156.21,3311.7 h60
  text "3.46" at 12806.04,3311.7 h60
  text "3" at 9956.79,3191.7 h60
  text "L3 PWR" at 10366.7,3191.7 h60
  text "CF-004" at 11296.44,3191.7 h60
  text "1.40mil" at 12156.21,3191.7 h60
  text "Dielectric 5" at 10366.7,3071.7 h60
  text "FR408HR" at 11296.44,3071.7 h60
  text "3.00mil" at 12156.21,3071.7 h60
  text "3.6" at 12806.04,3071.7 h60
  text "4" at 9956.79,2951.7 h60
  text "L4 GND" at 10366.7,2951.7 h60
  text "CF-004" at 11296.44,2951.7 h60
  text "1.40mil" at 12156.21,2951.7 h60
  text "Dielectric 7" at 10366.7,2831.7 h60
  text "FR408HR" at 11296.44,2831.7 h60
  text "9.20mil" at 12156.21,2831.7 h60
  text "3.68" at 12806.04,2831.7 h60
  text "5" at 9956.79,2711.7 h60
  text "L5 SIG" at 10366.7,2711.7 h60
  text "CF-004" at 11296.44,2711.7 h60
  text "1.40mil" at 12156.21,2711.7 h60
  text "Dielectric1" at 10366.7,2591.7 h60
  text "FR408HR" at 11296.44,2591.7 h60
  text "6.40mil" at 12156.21,2591.7 h60
  text "3.46" at 12806.04,2591.7 h60
  text "6" at 9956.79,2471.7 h60
  text "L6 GND" at 10366.7,2471.7 h60
  text "CF-004" at 11296.44,2471.7 h60
  text "1.40mil" at 12156.21,2471.7 h60
  text "Dielectric 8" at 10366.7,2351.7 h60
  text "FR408HR" at 11296.44,2351.7 h60
  text "9.20mil" at 12156.21,2351.7 h60
  text "3.68" at 12806.04,2351.7 h60
  text "7" at 9956.79,2231.7 h60
  text "L7 GND" at 10366.7,2231.7 h60
  text "CF-004" at 11296.44,2231.7 h60
  text "1.40mil" at 12156.21,2231.7 h60
  text "Dielectric 6" at 10366.7,2111.7 h60
  text "FR408HR" at 11296.44,2111.7 h60
  text "3.00mil" at 12156.21,2111.7 h60
  text "3.6" at 12806.04,2111.7 h60
  text "8" at 9956.79,1991.7 h60
  text "L8 PWR" at 10366.7,1991.7 h60
  text "CF-004" at 11296.44,1991.7 h60
  text "1.40mil" at 12156.21,1991.7 h60
  text "Dielectric 4" at 10366.7,1871.7 h60
  text "FR408HR" at 11296.44,1871.7 h60
  text "3.20mil" at 12156.21,1871.7 h60
  text "3.46" at 12806.04,1871.7 h60
  text "9" at 9956.79,1751.7 h60
  text "L9 GND" at 10366.7,1751.7 h60
  text "CF-004" at 11296.44,1751.7 h60
  text "1.40mil" at 12156.21,1751.7 h60
  text "Dielectric 2" at 10366.7,1631.7 h60
  text "FR408HR" at 11296.44,1631.7 h60
  text "5.00mil" at 12156.21,1631.7 h60
  text "3.62" at 12806.04,1631.7 h60
  text "10" at 9956.79,1511.7 h60
  text "Bottom Layer" at 10366.7,1511.7 h60
  text "1.40mil" at 12156.21,1511.7 h60
  text "Bottom Solder" at 10366.7,1391.7 h60
  text "Solder Resist" at 11296.44,1391.7 h60
  text "0.40mil" at 12156.21,1391.7 h60
  text "3.5" at 12806.04,1391.7 h60
  text "Bottom Overlay" at 10366.7,1271.7 h60
  text "Total board thickness:" at 9956.79,1151.7 h60
  text "62.00mil" at 12156.21,1151.7 h60
  text ".Layer_Name" at 577,-858.49 h60
Drill Drawing:
  drawing of 165 lines, arcs and shapes, not listed
  text "Symbol" at 24.58,5223.33 h48
  text "Count" at 372.5,5223.33 h48
  text "Hole Size" at 805.71,5223.33 h48
  text "Plated" at 1578.82,5223.33 h48
  text "Hole Type" at 1926.74,5223.33 h48
  text "Drill Layer Pair" at 2426.61,5223.33 h48
  text "Via/Pad" at 3432.98,5223.33 h48
  text "Pad Shape" at 3836.88,5223.33 h48
  text "Template" at 4570,5223.33 h48
  text "Description" at 5722.99,5223.33 h48
  text "Hole Tolerance (+)" at 6302.83,5223.33 h48
  text "Hole Tolerance (-)" at 7202.57,5223.33 h48
  text "1" at 372.5,5123.33 h40
  text "39.76mil (1.010mm)" at 805.71,5123.33 h40
  text "PTH" at 1578.82,5123.33 h40
  text "Slot" at 1926.74,5123.33 h40
  text "Top Layer - Bottom Layer" at 2426.61,5123.33 h40
  text "Pad" at 3432.98,5123.33 h40
  text "Rounded" at 3836.88,5123.33 h40
  text "r430_170h101_356r85" at 4570,5123.33 h40
  text "2" at 372.5,5023.33 h40
  text "25.59mil (0.650mm)" at 805.71,5023.33 h40
  text "NPTH" at 1578.82,5023.33 h40
  text "Round" at 1926.74,5023.33 h40
  text "Top Layer - Bottom Layer" at 2426.61,5023.33 h40
  text "Pad" at 3432.98,5023.33 h40
  text "Rounded" at 3836.88,5023.33 h40
  text "c65hn65m65p0" at 4570,5023.33 h40
  text "A" at 2.89,5013.34 h44.44
  text "2" at 372.5,4923.33 h40
  text "29.92mil (0.760mm)" at 805.71,4923.33 h40
  text "PTH" at 1578.82,4923.33 h40
  text "Slot" at 1926.74,4923.33 h40
  text "Top Layer - Bottom Layer" at 2426.61,4923.33 h40
  text "Pad" at 3432.98,4923.33 h40
  text "Rounded" at 3836.88,4923.33 h40
  text "r380_150h76_305r75" at 4570,4923.33 h40
  text "2" at 372.5,4823.33 h40
  text "50.00mil (1.270mm)" at 805.71,4823.33 h40
  text "NPTH" at 1578.82,4823.33 h40
  text "Round" at 1926.74,4823.33 h40
  text "Top Layer - Bottom Layer" at 2426.61,4823.33 h40
  text "Pad" at 3432.98,4823.33 h40
  text "Rounded" at 3836.88,4823.33 h40
  text "c127hn127" at 4570,4823.33 h40
  text "2" at 372.5,4723.33 h40
  text "55.12mil (1.400mm)" at 805.71,4723.33 h40
  text "PTH" at 1578.82,4723.33 h40
  text "Slot" at 1926.74,4723.33 h40
  text "Top Layer - Bottom Layer" at 2426.61,4723.33 h40
  text "Pad" at 3432.98,4723.33 h40
  text "Rounded Rectangle" at 3836.88,4723.33 h40
  text "r100_180h140_60r50m100_180p0" at 4570,4723.33 h40
  text "C" at 2.89,4713.34 h44.44
  text "2" at 372.5,4623.33 h40
  text "63.00mil (1.600mm)" at 805.71,4623.33 h40
  text "PTH" at 1578.82,4623.33 h40
  text "Round" at 1926.74,4623.33 h40
  text "Top Layer - Bottom Layer" at 2426.61,4623.33 h40
  text "Pad" at 3432.98,4623.33 h40
  text "Rounded" at 3836.88,4623.33 h40
  text "c221h160" at 4570,4623.33 h40
  text "2" at 372.5,4523.33 h40
  text "66.93mil (1.700mm)" at 805.71,4523.33 h40
  text "PTH" at 1578.82,4523.33 h40
  text "Slot" at 1926.74,4523.33 h40
  text "Top Layer - Bottom Layer" at 2426.61,4523.33 h40
  text "Pad" at 3432.98,4523.33 h40
  text "Rounded Rectangle" at 3836.88,4523.33 h40
  text "r100_210h170_60r50m100_210p0" at 4570,4523.33 h40
  text "B" at 2.89,4513.34 h44.44
  text "2" at 372.5,4423.33 h40
  text "105.91mil (2.690mm)" at 805.71,4423.33 h40
  text "NPTH" at 1578.82,4423.33 h40
  text "Round" at 1926.74,4423.33 h40
  text "Top Layer - Bottom Layer" at 2426.61,4423.33 h40
  text "Pad" at 3432.98,4423.33 h40
  text "Rounded" at 3836.88,4423.33 h40
  text "c-127hn269" at 4570,4423.33 h40
  text "2" at 372.5,4323.33 h40
  text "133.86mil (3.400mm)" at 805.71,4323.33 h40
  text "PTH" at 1578.82,4323.33 h40
  text "Round" at 1926.74,4323.33 h40
  text "Top Layer - Bottom Layer" at 2426.61,4323.33 h40
  text "Pad" at 3432.98,4323.33 h40
  text "Rounded" at 3836.88,4323.33 h40
  text "c550h340m550p0" at 4570,4323.33 h40
  text "3" at 372.5,4223.33 h40
  text "42.91mil (1.090mm)" at 805.71,4223.33 h40
  text "PTH" at 1578.82,4223.33 h40
  text "Round" at 1926.74,4223.33 h40
  text "Top Layer - Bottom Layer" at 2426.61,4223.33 h40
  text "Pad" at 3432.98,4223.33 h40
  text "(Mixed)" at 3836.88,4223.33 h40
  text "(Mixed)" at 4570,4223.33 h40
  text "6" at 372.5,4123.33 h40
  text "47.24mil (1.200mm)" at 805.71,4123.33 h40
  text "PTH" at 1578.82,4123.33 h40
  text "Round" at 1926.74,4123.33 h40
  text "Top Layer - Bottom Layer" at 2426.61,4123.33 h40
  text "Pad" at 3432.98,4123.33 h40
  text "(Mixed)" at 3836.88,4123.33 h40
  text "(Mixed)" at 4570,4123.33 h40
  text "10" at 372.5,4023.33 h40
  text "40.00mil (1.016mm)" at 805.71,4023.33 h40
  text "PTH" at 1578.82,4023.33 h40
  text "Round" at 1926.74,4023.33 h40
  text "Top Layer - Bottom Layer" at 2426.61,4023.33 h40
  text "Pad" at 3432.98,4023.33 h40
  text "(Mixed)" at 3836.88,4023.33 h40
  text "(Mixed)" at 4570,4023.33 h40
  text "12" at 372.5,3923.33 h40
  text "28.00mil (0.711mm)" at 805.71,3923.33 h40
  text "PTH" at 1578.82,3923.33 h40
  text "Round" at 1926.74,3923.33 h40
  text "Top Layer - Bottom Layer" at 2426.61,3923.33 h40
  text "Pad" at 3432.98,3923.33 h40
  text "(Mixed)" at 3836.88,3923.33 h40
  text "(Mixed)" at 4570,3923.33 h40
  text "14" at 372.5,3823.33 h40
  text "20.00mil (0.508mm)" at 805.71,3823.33 h40
  text "PTH" at 1578.82,3823.33 h40
  text "Round" at 1926.74,3823.33 h40
  text "Top Layer - Bottom Layer" at 2426.61,3823.33 h40
  text "Via" at 3432.98,3823.33 h40
  text "Rounded" at 3836.88,3823.33 h40
  text "v102h51m0mx0" at 4570,3823.33 h40
  text "32" at 372.5,3723.33 h40
  text "66.93mil (1.700mm)" at 805.71,3723.33 h40
  text "PTH" at 1578.82,3723.33 h40
  text "Round" at 1926.74,3723.33 h40
  text "Top Layer - Bottom Layer" at 2426.61,3723.33 h40
  text "Pad" at 3432.98,3723.33 h40
  text "Rounded" at 3836.88,3723.33 h40
  text "c260h170m260p0" at 4570,3723.33 h40
  text "44" at 372.5,3623.33 h40
  text "7.87mil (0.200mm)" at 805.71,3623.33 h40
  text "PTH" at 1578.82,3623.33 h40
  text "Round" at 1926.74,3623.33 h40
  text "Top Layer - Bottom Layer" at 2426.61,3623.33 h40
  text "Pad" at 3432.98,3623.33 h40
  text "Rounded" at 3836.88,3623.33 h40
  text "(Mixed)" at 4570,3623.33 h40
  text "1008" at 372.5,3523.33 h40
  text "8.00mil (0.203mm)" at 805.71,3523.33 h40
  text "PTH" at 1578.82,3523.33 h40
  text "Round" at 1926.74,3523.33 h40
  text "Top Layer - Bottom Layer" at 2426.61,3523.33 h40
  text "(Mixed)" at 3432.98,3523.33 h40
  text "Rounded" at 3836.88,3523.33 h40
  text "(Mixed)" at 4570,3523.33 h40
  text "1146 Total" at 372.5,3423.33 h40
  text "Slot definitions :" at 24.58,3320.01 h40
  text "Routed Path Length" at 722.37,3320.01 h40
  text "= Calculated from tool start centre position to tool end centre position." at 1466.82,3320.01 h40
  text "Hole Length" at 722.37,3246.7 h40
  text "= Routed Path Length + Tool Size = Slot length as defined in the PCB layout" at 1193.57,3246.7 h40
  text ".Layer_Name" at 577,-858.49 h60

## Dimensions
0,100 to 3900,100 on M2 Board Dimensions
100,2716.54 to 100,0 on M2 Board Dimensions
0,-400 to 1000,-400 on M2 Board Dimensions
